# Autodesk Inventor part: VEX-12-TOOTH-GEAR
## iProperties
Created: 2007-10
Part Number: VEX-12-TOOTH-GEAR
Document SubType Name: Modeling
Material: ABS Plastic
Density: 1.06 g/cm^3
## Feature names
1. Base1
